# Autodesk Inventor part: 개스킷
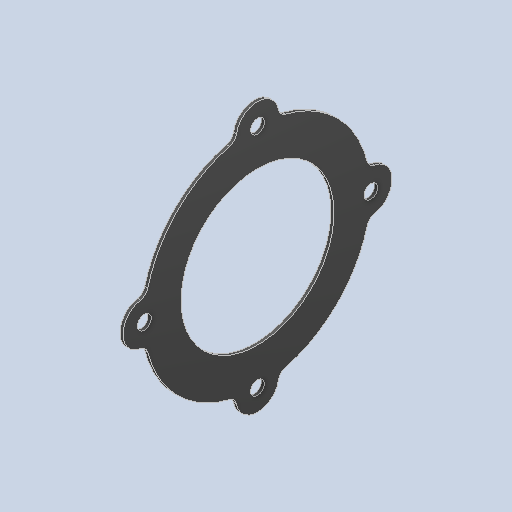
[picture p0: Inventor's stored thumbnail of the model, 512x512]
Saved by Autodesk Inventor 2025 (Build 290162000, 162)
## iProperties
Created: 2024-08
Part Number: 개스킷
Material: 황동, 연질 노란색
Document SubType Name: Modeling
Designer: SAMSUNG
Density: 8.47 g/cm^3
Appearance: 기본값
Author: jhkim
Sending System: Autodesk Inventor 2025
Preprocessor: ST-DEVELOPER v20
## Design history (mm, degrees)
feature "솔리드2"
node "솔리드1"
